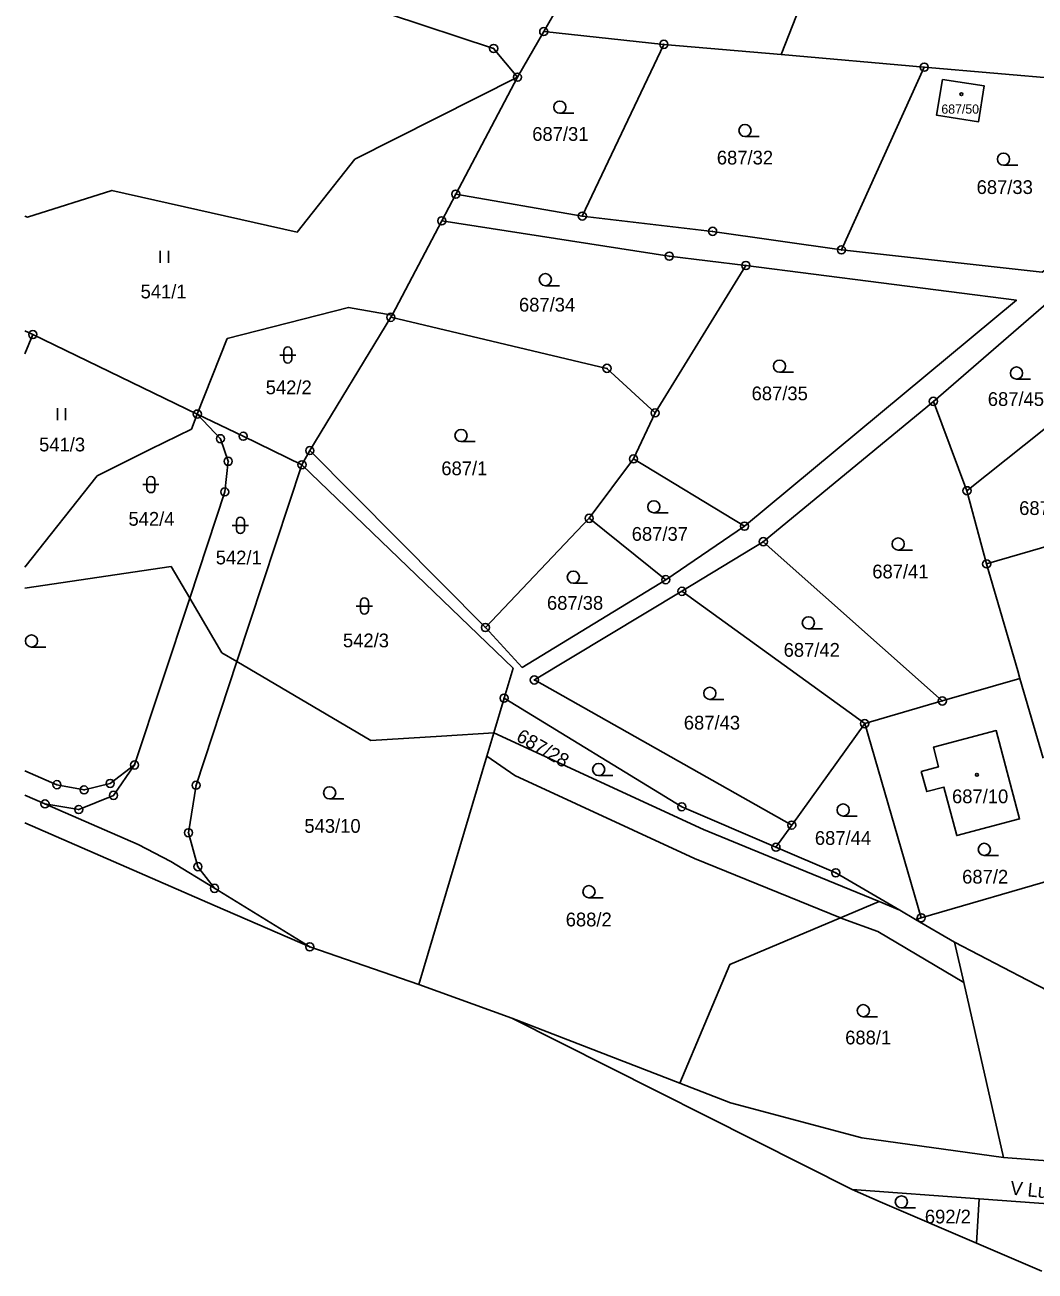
# Model space of a CAD drawing. Extents: x -749778 to -749372, y -967291 to -966955.
# Drawn here: x -749777.6 to -749652.7, y -967256 to -967101.9 of the extents above; entities that cross this region are included whole.
import ezdxf

# ---------------------------------------------------------------- set-up
doc = ezdxf.new("R2010")
doc.units = 0
for name, color, linetype in [('Hranice parcel', 7, 'Continuous'), ('Parcelní čísla', 7, 'Continuous'), ('Pop  PČ popisy', 7, 'Continuous'), ('Vnitřní kresba', 7, 'Continuous'), ('Značky bodu BP', 7, 'Continuous'), ('Značky budov', 7, 'Continuous'), ('Značky kultur', 7, 'Continuous')]:
    doc.layers.add(name, color=color, linetype=linetype)

msp = doc.modelspace()

# ---------------------------------------------------------------- linework, layer by layer
at = {"layer": 'Hranice parcel'}
for p, q in [((-749684.12, -967105.59), (-749664.5, -967054.98)), ((-749699.81, -967078.98), (-749713.49, -967102.74)), ((-749713.49, -967102.74), (-749716.74, -967108.38)), ((-749698.64, -967104.32), (-749713.49, -967102.74)), ((-749708.72, -967125.55), (-749698.64, -967104.32)), ((-749684.12, -967105.59), (-749698.64, -967104.32)), ((-749666.45, -967107.14), (-749684.12, -967105.59)), ((-749676.68, -967129.73), (-749666.45, -967107.14)), ((-749643.43, -967109.15), (-749666.45, -967107.14)), ((-749716.74, -967108.38), (-749724.36, -967122.84)), ((-749724.36, -967122.84), (-749726.1, -967126.14)), ((-749724.36, -967122.84), (-749708.72, -967125.55)), ((-749726.1, -967126.14), (-749732.24, -967137.8)), ((-749699.72, -967149.89), (-749688.5, -967131.66)), ((-749665.32, -967148.46), (-749648.79, -967134.15)), ((-749732.24, -967137.8), (-749732.4, -967138.07)), ((-749732.4, -967138.07), (-749742.41, -967154.55)), ((-749777.63, -967139.73), (-749776.65, -967140.2)), ((-749777.63, -967142.59), (-749776.65, -967140.2)), ((-749776.65, -967140.2), (-749756.32, -967150.03)), ((-749644.47, -967146.16), (-749661.16, -967159.51)), ((-749686.34, -967165.81), (-749665.32, -967148.46)), ((-749661.16, -967159.51), (-749665.32, -967148.46)), ((-749702.39, -967155.58), (-749699.72, -967149.89)), ((-749742.41, -967154.55), (-749743.38, -967156.3)), ((-749742.41, -967154.55), (-749720.7, -967176.42)), ((-749751.42, -967180.64), (-749743.38, -967156.3)), ((-749707.87, -967162.92), (-749702.39, -967155.58)), ((-749702.39, -967155.58), (-749688.67, -967163.89)), ((-749661.16, -967159.51), (-749658.73, -967168.56)), ((-749720.7, -967176.42), (-749707.87, -967162.92)), ((-749707.87, -967162.92), (-749698.4, -967170.51)), ((-749698.4, -967170.51), (-749688.67, -967163.89)), ((-749639.53, -967162.97), (-749658.73, -967168.56)), ((-749696.41, -967171.95), (-749686.34, -967165.81)), ((-749686.34, -967165.81), (-749664.21, -967185.51)), ((-749757.25, -967172.78), (-749764.07, -967193.42)), ((-749696.41, -967171.95), (-749673.81, -967188.31)), ((-749654.61, -967182.72), (-749664.21, -967185.51)), ((-749651.74, -967192.56), (-749654.61, -967182.72)), ((-749718.39, -967185.16), (-749719.66, -967189.45)), ((-749664.21, -967185.51), (-749673.81, -967188.31)), ((-749682.82, -967200.86), (-749673.81, -967188.31)), ((-749673.81, -967188.31), (-749666.82, -967212.31)), ((-749754.11, -967210.82), (-749777.63, -967200.58)), ((-749684.78, -967203.59), (-749682.82, -967200.86)), ((-749666.82, -967212.31), (-749647.62, -967206.72)), ((-749672.03, -967210.32), (-749669.47, -967211.37)), ((-749754.11, -967210.82), (-749742.41, -967215.91)), ((-749669.47, -967211.37), (-749667.52, -967212.51)), ((-749667.52, -967212.51), (-749666.82, -967212.31)), ((-749667.52, -967212.51), (-749662.69, -967215.35)), ((-749728.94, -967220.55), (-749742.41, -967215.91)), ((-749728.94, -967220.55), (-749717.43, -967224.74)), ((-749717.43, -967224.74), (-749696.68, -967232.76)), ((-749717.43, -967224.74), (-749675.37, -967245.93)), ((-749675.37, -967245.93), (-749659.64, -967247.08)), ((-749675.37, -967245.93), (-749671.88, -967247.43)), ((-749659.64, -967247.08), (-749659.97, -967252.54)), ((-749671.88, -967247.43), (-749659.97, -967252.54)), ((-749651.9, -967256), (-749659.97, -967252.54))]:
    msp.add_line(p, q, dxfattribs=at)
for points in [[(-749716.74, -967108.38), (-749719.68, -967104.83), (-749745.68, -967096.2), (-749753.84, -967093.49)], [(-749777.63, -967125.56), (-749777.33, -967125.69), (-749766.87, -967122.37), (-749743.96, -967127.54), (-749736.83, -967118.52), (-749716.74, -967108.38)], [(-749664.18, -967108.65), (-749659.04, -967109.43), (-749659.75, -967113.91), (-749664.91, -967113.09), (-749664.18, -967108.65)], [(-749676.68, -967129.73), (-749651.87, -967132.49), (-749649.4, -967130.69), (-749637.12, -967116.63), (-749632.88, -967109.8)], [(-749708.72, -967125.55), (-749692.61, -967127.44), (-749676.68, -967129.73)], [(-749688.5, -967131.66), (-749697.97, -967130.51), (-749726.1, -967126.14)], [(-749688.67, -967163.89), (-749655.05, -967135.96), (-749688.5, -967131.66)], [(-749756.32, -967150.03), (-749752.62, -967140.7), (-749737.63, -967136.85), (-749732.24, -967137.8)], [(-749699.72, -967149.89), (-749705.67, -967144.38), (-749732.4, -967138.07)], [(-749777.63, -967168.98), (-749768.68, -967157.66), (-749762.09, -967154.39), (-749757.05, -967151.88), (-749756.32, -967150.03)], [(-749756.32, -967150.03), (-749753.46, -967153.08), (-749752.5, -967155.87), (-749752.92, -967159.66), (-749757.25, -967172.78)], [(-749743.38, -967156.3), (-749750.64, -967152.77), (-749756.32, -967150.03)], [(-749743.38, -967156.3), (-749717.28, -967181.45), (-749718.39, -967185.16)], [(-749658.73, -967168.56), (-749654.88, -967181.79), (-749654.61, -967182.72)], [(-749777.63, -967171.57), (-749759.56, -967168.86), (-749757.25, -967172.78)], [(-749720.7, -967176.42), (-749716.14, -967181.35), (-749698.4, -967170.51)], [(-749751.42, -967180.64), (-749753.27, -967179.55), (-749757.25, -967172.78)], [(-749682.82, -967200.86), (-749714.65, -967182.91), (-749696.41, -967171.95)], [(-749742.41, -967215.91), (-749754.19, -967208.67), (-749756.24, -967206), (-749757.41, -967201.8), (-749756.47, -967195.93), (-749751.42, -967180.64)], [(-749751.42, -967180.64), (-749734.88, -967190.41), (-749726.13, -967189.86), (-749719.66, -967189.45)], [(-749684.78, -967203.59), (-749696.42, -967198.59), (-749718.39, -967185.16)], [(-749719.66, -967189.45), (-749720.52, -967192.32), (-749728.94, -967220.55)], [(-749719.66, -967189.45), (-749693.75, -967201.38), (-749685.61, -967204.73), (-749672.03, -967210.32)], [(-749666.81, -967194.21), (-749664.68, -967193.64), (-749665.32, -967191.23), (-749657.54, -967189.17), (-749654.65, -967200.09), (-749662.43, -967202.15), (-749664.01, -967196.16), (-749666.14, -967196.72), (-749666.81, -967194.21)], [(-749764.07, -967193.42), (-749766.68, -967197.18), (-749770.97, -967198.93), (-749775.15, -967198.23), (-749777.63, -967197.15)], [(-749777.63, -967194.14), (-749773.68, -967195.86), (-749770.31, -967196.5), (-749767.09, -967195.7), (-749764.07, -967193.42)], [(-749669.47, -967211.37), (-749677.38, -967206.76), (-749684.78, -967203.59)], [(-749672.03, -967210.32), (-749676.78, -967212.32), (-749690.48, -967218.09), (-749696.68, -967232.76)], [(-749662.69, -967215.35), (-749653.68, -967220.04), (-749641.76, -967226.16), (-749629.68, -967230.35), (-749627.23, -967231.85), (-749624.5, -967234)], [(-749656.66, -967241.94), (-749661.57, -967220.3), (-749662.69, -967215.35)], [(-749696.68, -967232.76), (-749690.38, -967235.19), (-749674.18, -967239.51), (-749656.66, -967241.94)], [(-749656.66, -967241.94), (-749647.41, -967242.66), (-749642.21, -967243.07), (-749637.32, -967244.05), (-749636.15, -967244.28), (-749627.26, -967246.06)], [(-749659.64, -967247.08), (-749637.51, -967248.69), (-749619.32, -967252.61)]]:
    msp.add_lwpolyline(points, dxfattribs=at)
at = {"layer": 'Vnitřní kresba'}
for p, q in [((-749720.52, -967192.32), (-749717.06, -967194.72)), ((-749717.06, -967194.72), (-749694.85, -967204.98)), ((-749763.63, -967203.25), (-749775.15, -967198.23)), ((-749759.59, -967205.36), (-749763.63, -967203.25)), ((-749754.19, -967208.67), (-749759.59, -967205.36)), ((-749694.85, -967204.98), (-749676.78, -967212.32)), ((-749676.78, -967212.32), (-749676.52, -967212.43)), ((-749676.52, -967212.43), (-749672.18, -967214.02)), ((-749672.18, -967214.02), (-749661.57, -967220.3))]:
    msp.add_line(p, q, dxfattribs=at)
at = {"layer": 'Značky bodu BP'}
for centre, radius in [((-749713.49, -967102.74), 0.5), ((-749713.49, -967102.74), 0.0303), ((-749698.64, -967104.32), 0.5), ((-749719.68, -967104.83), 0.5), ((-749719.68, -967104.83), 0.0303), ((-749698.64, -967104.32), 0.0303), ((-749666.45, -967107.14), 0.5), ((-749666.45, -967107.14), 0.0303), ((-749716.74, -967108.38), 0.5), ((-749716.74, -967108.38), 0.0303), ((-749724.36, -967122.84), 0.5), ((-749724.36, -967122.84), 0.0303), ((-749726.1, -967126.14), 0.5), ((-749708.72, -967125.55), 0.5), ((-749708.72, -967125.55), 0.0303), ((-749726.1, -967126.14), 0.0303), ((-749692.61, -967127.44), 0.5), ((-749692.61, -967127.44), 0.0303), ((-749697.97, -967130.51), 0.5), ((-749676.68, -967129.73), 0.5), ((-749676.68, -967129.73), 0.0303), ((-749697.97, -967130.51), 0.0303), ((-749688.5, -967131.66), 0.5), ((-749688.5, -967131.66), 0.0303), ((-749732.4, -967138.07), 0.5), ((-749732.4, -967138.07), 0.0303), ((-749776.65, -967140.2), 0.5), ((-749776.65, -967140.2), 0.0303), ((-749705.67, -967144.38), 0.5), ((-749705.67, -967144.38), 0.0303), ((-749665.32, -967148.46), 0.5), ((-749665.32, -967148.46), 0.0303), ((-749756.32, -967150.03), 0.5), ((-749756.32, -967150.03), 0.0303), ((-749699.72, -967149.89), 0.5), ((-749699.72, -967149.89), 0.0303), ((-749753.46, -967153.08), 0.5), ((-749753.46, -967153.08), 0.0303), ((-749750.64, -967152.77), 0.5), ((-749750.64, -967152.77), 0.0303), ((-749742.41, -967154.55), 0.5), ((-749742.41, -967154.55), 0.0303), ((-749752.5, -967155.87), 0.5), ((-749752.5, -967155.87), 0.0303), ((-749743.38, -967156.3), 0.5), ((-749743.38, -967156.3), 0.0303), ((-749702.39, -967155.58), 0.5), ((-749702.39, -967155.58), 0.0303), ((-749752.92, -967159.66), 0.5), ((-749661.16, -967159.51), 0.5), ((-749661.16, -967159.51), 0.0303), ((-749752.92, -967159.66), 0.0303), ((-749707.87, -967162.92), 0.5), ((-749707.87, -967162.92), 0.0303), ((-749688.67, -967163.89), 0.5), ((-749688.67, -967163.89), 0.0303), ((-749686.34, -967165.81), 0.5), ((-749686.34, -967165.81), 0.0303), ((-749658.73, -967168.56), 0.5), ((-749658.73, -967168.56), 0.0303), ((-749698.4, -967170.51), 0.5), ((-749698.4, -967170.51), 0.0303), ((-749696.41, -967171.95), 0.5), ((-749696.41, -967171.95), 0.0303), ((-749720.7, -967176.42), 0.5), ((-749720.7, -967176.42), 0.0303), ((-749714.65, -967182.91), 0.5), ((-749714.65, -967182.91), 0.0303), ((-749718.39, -967185.16), 0.5), ((-749718.39, -967185.16), 0.0303), ((-749664.21, -967185.51), 0.5), ((-749664.21, -967185.51), 0.0303), ((-749673.81, -967188.31), 0.5), ((-749673.81, -967188.31), 0.0303), ((-749764.07, -967193.42), 0.5), ((-749764.07, -967193.42), 0.0303), ((-749773.68, -967195.86), 0.5), ((-749773.68, -967195.86), 0.0303), ((-749770.31, -967196.5), 0.5), ((-749770.31, -967196.5), 0.0303), ((-749767.09, -967195.7), 0.5), ((-749767.09, -967195.7), 0.0303), ((-749756.47, -967195.93), 0.5), ((-749756.47, -967195.93), 0.0303), ((-749775.15, -967198.23), 0.5), ((-749766.68, -967197.18), 0.5), ((-749766.68, -967197.18), 0.0303), ((-749696.42, -967198.59), 0.5), ((-749775.15, -967198.23), 0.0303), ((-749770.97, -967198.93), 0.5), ((-749770.97, -967198.93), 0.0303), ((-749696.42, -967198.59), 0.0303), ((-749682.82, -967200.86), 0.5), ((-749682.82, -967200.86), 0.0303), ((-749757.41, -967201.8), 0.5), ((-749757.41, -967201.8), 0.0303), ((-749684.78, -967203.59), 0.5), ((-749684.78, -967203.59), 0.0303), ((-749756.24, -967206), 0.5), ((-749756.24, -967206), 0.0303), ((-749677.38, -967206.76), 0.5), ((-749677.38, -967206.76), 0.0303), ((-749754.19, -967208.67), 0.5), ((-749754.19, -967208.67), 0.0303), ((-749666.82, -967212.31), 0.5), ((-749666.82, -967212.31), 0.0303), ((-749742.41, -967215.91), 0.5), ((-749742.41, -967215.91), 0.0303)]:
    msp.add_circle(centre, radius, dxfattribs=at)
at = {"layer": 'Značky budov'}
for centre in [(-749661.85, -967110.48), (-749659.93, -967194.64)]:
    msp.add_circle(centre, 0.175, dxfattribs=at)
at = {"layer": 'Značky kultur'}
for p, q in [((-749711.5, -967112.83), (-749709.75, -967112.83)), ((-749688.61, -967115.71), (-749686.86, -967115.71)), ((-749656.64, -967119.26), (-749654.89, -967119.26)), ((-749760.89, -967131.35), (-749760.89, -967129.85)), ((-749759.89, -967131.35), (-749759.89, -967129.85)), ((-749713.29, -967134.16), (-749711.54, -967134.16)), ((-749745.63, -967142.23), (-749745.63, -967143.23)), ((-749744.63, -967143.23), (-749744.63, -967142.23)), ((-749746.13, -967142.73), (-749744.13, -967142.73)), ((-749684.34, -967144.87), (-749682.59, -967144.87)), ((-749655.04, -967145.71), (-749653.29, -967145.71)), ((-749773.62, -967150.79), (-749773.62, -967149.29)), ((-749772.62, -967150.79), (-749772.62, -967149.29)), ((-749723.71, -967153.44), (-749721.96, -967153.44)), ((-749763.06, -967158.75), (-749761.06, -967158.75)), ((-749762.56, -967158.25), (-749762.56, -967159.25)), ((-749761.56, -967159.25), (-749761.56, -967158.25)), ((-749699.87, -967162.24), (-749698.12, -967162.24)), ((-749751.99, -967163.8), (-749749.99, -967163.8)), ((-749751.49, -967163.3), (-749751.49, -967164.3)), ((-749750.49, -967164.3), (-749750.49, -967163.3)), ((-749669.66, -967166.85), (-749667.91, -967166.85)), ((-749709.83, -967170.94), (-749708.08, -967170.94)), ((-749736.16, -967173.27), (-749736.16, -967174.27)), ((-749735.16, -967174.27), (-749735.16, -967173.27)), ((-749736.66, -967173.77), (-749734.66, -967173.77)), ((-749680.77, -967176.6), (-749679.02, -967176.6)), ((-749776.81, -967178.84), (-749775.06, -967178.84)), ((-749692.96, -967185.31), (-749691.21, -967185.31)), ((-749706.7, -967194.73), (-749704.95, -967194.73)), ((-749739.96, -967197.62), (-749738.21, -967197.62)), ((-749676.48, -967199.74), (-749674.73, -967199.74)), ((-749659.02, -967204.61), (-749657.27, -967204.61)), ((-749707.9, -967209.84), (-749706.15, -967209.84)), ((-749673.98, -967224.55), (-749672.23, -967224.55)), ((-749669.27, -967248.2), (-749667.52, -967248.2))]:
    msp.add_line(p, q, dxfattribs=at)
for centre in [(-749711.5, -967112.08), (-749688.61, -967114.96), (-749656.64, -967118.51), (-749713.29, -967133.41), (-749684.34, -967144.12), (-749655.04, -967144.96), (-749723.71, -967152.69), (-749699.87, -967161.49), (-749669.66, -967166.1), (-749709.83, -967170.19), (-749680.77, -967175.85), (-749776.81, -967178.09), (-749692.96, -967184.56), (-749706.7, -967193.98), (-749739.96, -967196.87), (-749676.48, -967198.99), (-749659.02, -967203.86), (-749707.9, -967209.09), (-749673.98, -967223.8), (-749669.27, -967247.45)]:
    msp.add_circle(centre, 0.75, dxfattribs=at)
for centre, start, end in [((-749745.13, -967142.23), 0, 180), ((-749745.13, -967143.23), 180, 359.9879), ((-749762.06, -967158.25), 0, 180), ((-749762.06, -967159.25), 180, 359.9879), ((-749750.99, -967163.3), 0, 180), ((-749750.99, -967164.3), 180, 359.9879), ((-749735.66, -967173.27), 0, 180), ((-749735.66, -967174.27), 180, 359.9879)]:
    msp.add_arc(centre, 0.5, start, end, dxfattribs=at)

# ---------------------------------------------------------------- texts
at = {"layer": 'Parcelní čísla'}
for s, height, p in [('687/50', 1.139, (-749664.33, -967112.89)), ('687/31', 1.7, (-749714.91, -967116.25)), ('687/32', 1.7, (-749692.09, -967119.17)), ('687/33', 1.7, (-749659.97, -967122.82)), ('541/1', 1.7, (-749763.33, -967135.73)), ('687/34', 1.7, (-749716.55, -967137.36)), ('542/2', 1.7, (-749747.86, -967147.58)), ('687/35', 1.7, (-749687.79, -967148.33)), ('687/45', 1.7, (-749658.59, -967149.03)), ('541/3', 1.7, (-749775.88, -967154.65)), ('687/1', 1.7, (-749726.15, -967157.59)), ('687/19', 1.7, (-749654.71, -967162.51)), ('542/4', 1.7, (-749764.83, -967163.84)), ('687/37', 1.7, (-749702.61, -967165.7)), ('542/1', 1.7, (-749754.04, -967168.62)), ('687/41', 1.7, (-749672.87, -967170.35)), ('687/38', 1.7, (-749713.09, -967174.23)), ('542/3', 1.7, (-749738.31, -967178.87)), ('687/42', 1.7, (-749683.83, -967180.04)), ('687/43', 1.7, (-749696.17, -967189.04)), ('687/10', 1.7, (-749663.01, -967198.15)), ('543/10', 1.7, (-749743.08, -967201.81)), ('687/44', 1.7, (-749679.97, -967203.3)), ('687/2', 1.7, (-749661.76, -967208.09)), ('688/2', 1.7, (-749710.77, -967213.38)), ('688/1', 1.7, (-749676.22, -967227.97)), ('692/2', 1.7, (-749666.37, -967250.11))]:
    msp.add_text(s, height=height, dxfattribs=at).set_placement(p)
msp.add_text('687/28', height=1.7, rotation=330, dxfattribs=at).set_placement((-749717.02, -967190.34))
at = {"layer": 'Pop  PČ popisy'}
msp.add_text('V Lukách', height=1.7, rotation=354, dxfattribs=at).set_placement((-749655.88, -967246.53))

doc.saveas('drawing.dxf')
